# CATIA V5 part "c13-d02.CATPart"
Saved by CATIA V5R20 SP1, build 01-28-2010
Part number: Part1
Bounding box of the stored display mesh (mm): x -33 to 33, y -200.819 to 48, z -35 to 35
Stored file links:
  D:\v5_r20\psrt_files_downloaded\c13-catia-v5r20-prt\c13-catia-v5r20-figr-13-17\c13-d02.CATPart
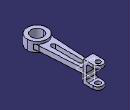
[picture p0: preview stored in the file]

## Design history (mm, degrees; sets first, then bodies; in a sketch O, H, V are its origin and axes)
Body1 (main body)
  Sketch1 on yz-plane, origin (0, 0, 0), H (0, 1, 0), V (0, 0, 1)
    line L1 (0, 0) -> (0, -35)
    point P1 (0, -35)
    line L2 (0, -35) -> (48, -35)
    point P2 (48, -35)
    line L3 (48, -35) -> (48, -25)
    point P3 (48, -25)
    line L4 (48, -25) -> (10, -25)
    point P4 (10, -25)
    line L5 (10, -25) -> (10, 0)
    point P5 (10, 0)
    point P6 (0, 0)
    point P7 (0, 0)
    point P8 (0, 35)
    point P9 (48, 35)
    point P10 (48, 25)
    point P11 (10, 25)
    point P12 (10, 0)
    point P13 (0, 0)
    line L6 (0, 0) -> (0, 35)
    line L7 (0, 35) -> (48, 35)
    line L8 (48, 35) -> (48, 25)
    line L9 (48, 25) -> (10, 25)
    line L10 (10, 25) -> (10, 0)
    length L8 = 10
    distance P3 L9 = 50
    length L2 = 48
    distance L10 L6 = 10
    vertical: L1 V, L3 V, L5 V
    horizontal: L2 H, L4 H
    symmetry: O P7 H, P1 P8 H, P2 P9 H, P3 P10 H, P4 P11 H, P5 P12 H, P6 P13 H, L1 L6 H, L2 L7 H, L3 L8 H, L4 L9 H, L5 L10 H
    coincidence: P13 P7, P12 P5, P6 P7
  Pad1: profile Sketch1, direction (1, 0, 0), length 16, mirrored extent
  Sketch2 on xy-plane, origin (0, 0, 0), H (1, 0, 0), V (0, 1, 0)
    circle A1 centre (0, -168) radius 33
    point P1 (0, -168)
    circle A2 centre (0, -168) radius 20
    distance P1 H = 168
    radius A1 = 33
    radius A2 = 20
    coincidence: P1 V
  Pad2: profile Sketch2, direction (0, 0, 1), length 16, mirrored extent
  Sketch3 on xy-plane, origin (0, 0, 0), H (1, 0, 0), V (0, 1, 0)
    line L1 (-16, 0) -> (-25, -146.4593)
    point P1 (-16, 0)
    point P2 (-25, -146.4593)
    line L2 (16, 0) -> (25, -146.4593)
    point P3 (16, 0)
    point P4 (25, -146.4593)
    reference projected line E1 (16, 48) -> (16, 0) from edge [face of Pad1 | face of Pad1]
    reference projected line E2 (-16, 48) -> (-16, 0) from edge [face of Pad1 | face of Pad1]
    projected circle E3 centre (0, -168) radius 33 from edge [face of Pad2 | face of Pad2]
    projected arc E4 centre (0, -168) radius 33 from (25, -146.4593) to (-25, -146.4593) ccw from edge [face of Pad2 | face of Pad2]
    line L3 (-16, 0) -> (16, 0)
    distance P4 P2 H = 50
    coincidence: P1 H, P3 H, P3 E1, P1 E2, P2 E3, P4 E3
    symmetry: P4 P2 V
    horizontal: L3 H
  Pad3: profile Sketch3, direction (0, 0, 1), length 8, mirrored extent
  Fillet1: radius 6, on edge [face of Pad1 | face of Pad3]; edge [face of Pad3 | face of Pad1]; edge [face of Pad1 | face of Pad1] (x2)
  Fillet2: radius 30, on edge [face of Pad3 | face of Pad2]; edge [face of Pad2 | face of Pad3]
  TritangentFillet1: Face1 face of Pad1, RemoveFace face of Pad1, Face2 face of Pad1
  TritangentFillet2: Face1 face of Pad1, RemoveFace face of Pad1, Face2 face of Pad1
  Sketch4 on face of Pad1, origin (2.8418, 32, 35), H (1, 0, 0), V (0, 1, 0)
    point P1 (-2.8418, 0)
    reference projected arc E1 centre (-2.8418, 0) radius 16 from (13.1582, 0) to (-18.8418, 0) ccw from edge [face of Pad1 | face of TritangentFillet1]
    concentricity: P1 E1
  Hole1: placed by Sketch4, at (0, 32, 35) direction (0, 0, -1), diameter 16, through (limit type 3)
  Sketch5 on face of Pad3, origin (0, 0, 8), H (1, 0, 0), V (0, 1, 0)
    construction line L1 (0, -25) -> (0, -115)
    point P1 (0, -25)
    line L2 (7, -25) -> (7, -115)
    line L3 (-7, -115) -> (-7, -25)
    arc A1 centre (0, -115) radius 7 from (7, -115) to (-7, -115) cw
    arc A2 centre (0, -25) radius 7 from (-7, -25) to (7, -25) cw
    distance P1 H = 25
    length L1 = 90
    radius A1 = 7
    coincidence: P1 V
    vertical: L1 V
    tangency: A1 L2, A2 L2, A1 L3, A2 L3
    parallelism: L1 L2
  Pocket1: profile Sketch5, direction (0, 0, -1), through (limit type 3)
